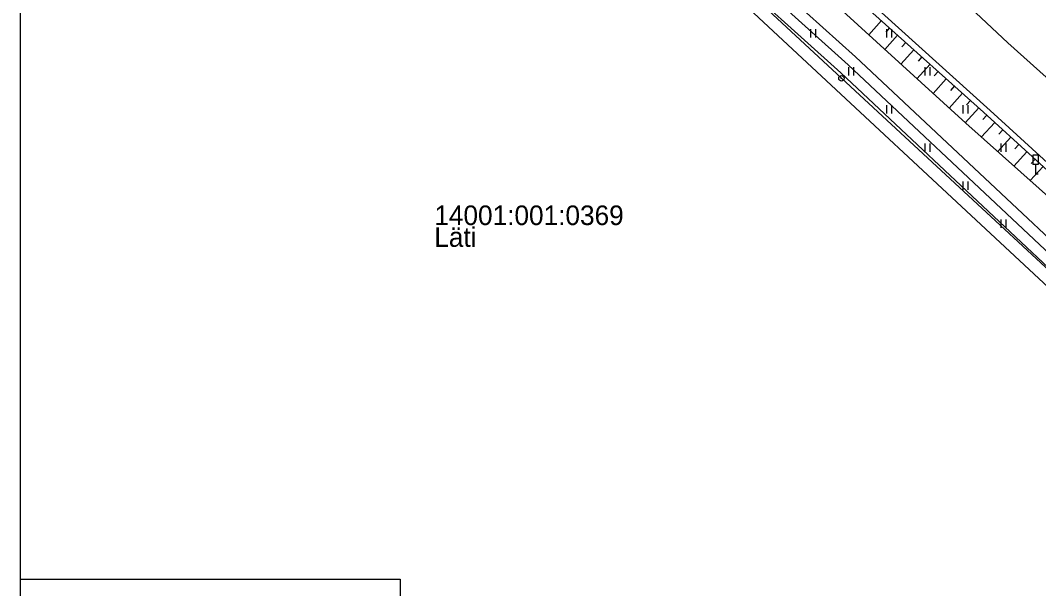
# Model space of a CAD drawing. Extents: x 567864 to 568657, y 6579839 to 6580994.
# Drawn here: x 568384.7 to 568478.2, y 6580358.5 to 6580410.7 of the extents above; entities that cross this region are included whole.
import ezdxf

# ---------------------------------------------------------------- set-up
doc = ezdxf.new("R2010")
doc.units = 0
for name, color, linetype in [('HALJASTUS', 7, 'Continuous'), ('KASUTUSALA', 7, 'Continuous'), ('KPOHULIIN', 7, 'Continuous'), ('LIIKLUS', 7, 'Continuous'), ('PIIR', 7, 'Continuous'), ('POST', 7, 'Continuous'), ('PR_SIDE', 7, 'Continuous'), ('RELJEEF', 7, 'Continuous'), ('TEE', 7, 'Continuous'), ('VORMISTUS_3', 7, 'Continuous')]:
    doc.layers.add(name, color=color, linetype=linetype)

msp = doc.modelspace()

# ---------------------------------------------------------------- linework, layer by layer
at = {"layer": 'HALJASTUS'}
for p, q in [((568457.272, 6580409.881), (568457.272, 6580409.119)), ((568457.728, 6580409.881), (568457.728, 6580409.119)), ((568464.272, 6580409.881), (568464.272, 6580409.119)), ((568464.728, 6580409.881), (568464.728, 6580409.119)), ((568460.772, 6580406.381), (568460.772, 6580405.619)), ((568461.228, 6580406.381), (568461.228, 6580405.619)), ((568467.772, 6580406.381), (568467.772, 6580405.619)), ((568468.228, 6580406.381), (568468.228, 6580405.619)), ((568464.272, 6580402.881), (568464.272, 6580402.119)), ((568464.728, 6580402.881), (568464.728, 6580402.119)), ((568471.272, 6580402.881), (568471.272, 6580402.119)), ((568471.728, 6580402.881), (568471.728, 6580402.119)), ((568467.772, 6580399.381), (568467.772, 6580398.619)), ((568468.228, 6580399.381), (568468.228, 6580398.619)), ((568474.772, 6580399.381), (568474.772, 6580398.619)), ((568475.228, 6580399.381), (568475.228, 6580398.619)), ((568471.272, 6580395.881), (568471.272, 6580395.119)), ((568471.728, 6580395.881), (568471.728, 6580395.119)), ((568474.772, 6580392.381), (568474.772, 6580391.619)), ((568475.228, 6580392.381), (568475.228, 6580391.619))]:
    msp.add_line(p, q, dxfattribs=at)
at = {"layer": 'KASUTUSALA'}
msp.add_lwpolyline([(568493.207, 6580374.737), (568460.062, 6580405.872), (568437.58, 6580426.106), (568418.255, 6580443.353), (568417.794, 6580443.764), (568417.1, 6580444.45), (568402.76, 6580458.616), (568388.236, 6580470.827), (568387.31, 6580471.69), (568385.679, 6580473.21), (568386.212, 6580473.528), (568388.359, 6580473.336), (568404.109, 6580460.095), (568418.602, 6580445.777), (568429.97, 6580456.218), (568431.455, 6580454.865), (568420.072, 6580444.412), (568438.915, 6580427.595), (568461.416, 6580407.344), (568494.568, 6580376.202)], dxfattribs=at)
at = {"layer": 'KPOHULIIN'}
msp.add_lwpolyline([(568508.43, 6580360.63), (568460.118, 6580405.359), (568402.883, 6580458.504), (568384.68, 6580466.246)], dxfattribs=at)
at = {"layer": 'LIIKLUS'}
for p, q in [((568477.701, 6580398.29), (568477.701, 6580397.44)), ((568478.201, 6580398.29), (568477.701, 6580398.29)), ((568478.201, 6580397.44), (568477.701, 6580397.44)), ((568477.951, 6580397.44), (568477.951, 6580396.54)), ((568478.201, 6580398.29), (568478.201, 6580397.44)), ((568478.201, 6580396.54), (568477.951, 6580396.54))]:
    msp.add_line(p, q, dxfattribs=at)
at = {"layer": 'PIIR'}
for points in [[(568508.43, 6580358.861), (568387.31, 6580471.69), (568384.68, 6580474.141)], [(568384.68, 6580470.154), (568387.31, 6580471.69), (568508.43, 6580358.861)]]:
    msp.add_lwpolyline(points, dxfattribs=at)
at = {"layer": 'POST'}
for radius in [0.25, 0.0234]:
    msp.add_circle((568460.118, 6580405.359), radius, dxfattribs=at)
at = {"layer": 'PR_SIDE'}
msp.add_lwpolyline([(568418.48, 6580444.494), (568438.248, 6580426.851), (568460.739, 6580406.609), (568493.888, 6580375.47), (568520.606, 6580350.928), (568532.176, 6580339.842), (568577.376, 6580298.14), (568583.801, 6580292.735), (568596.758, 6580277.054), (568604.332, 6580268.007), (568619.547, 6580250.982), (568628.574, 6580238.417), (568627.426, 6580222.172)], dxfattribs=at)
at = {"layer": 'RELJEEF'}
for p, q in [((568463.792, 6580410.661), (568462.629, 6580409.362)), ((568464.537, 6580409.994), (568464.186, 6580409.602)), ((568465.282, 6580409.326), (568464.106, 6580408.013)), ((568466.027, 6580408.659), (568465.672, 6580408.263)), ((568466.771, 6580407.992), (568465.582, 6580406.665)), ((568467.516, 6580407.325), (568467.158, 6580406.925)), ((568468.261, 6580406.658), (568467.059, 6580405.316)), ((568469.006, 6580405.991), (568468.644, 6580405.586)), ((568469.751, 6580405.323), (568468.536, 6580403.967)), ((568471.241, 6580403.989), (568470.013, 6580402.619)), ((568470.496, 6580404.656), (568470.13, 6580404.247)), ((568471.986, 6580403.322), (568471.615, 6580402.909)), ((568472.731, 6580402.655), (568471.49, 6580401.27)), ((568474.212, 6580401.311), (568472.97, 6580399.95)), ((568473.473, 6580401.985), (568473.098, 6580401.574)), ((568474.951, 6580400.637), (568474.581, 6580400.231)), ((568475.69, 6580399.963), (568474.463, 6580398.619)), ((568476.428, 6580399.289), (568476.063, 6580398.889)), ((568477.167, 6580398.615), (568475.957, 6580397.288)), ((568477.906, 6580397.942), (568477.545, 6580397.546)), ((568478.645, 6580397.268), (568477.45, 6580395.957))]:
    msp.add_line(p, q, dxfattribs=at)
for points in [[(568508.43, 6580369.908), (568508.363, 6580369.97), (568491.192, 6580385.824), (568473.185, 6580402.248), (568453.996, 6580419.435), (568439.254, 6580432.576), (568424.484, 6580446.124), (568410.28, 6580459.769), (568392.732, 6580475.544), (568387.587, 6580476.456), (568384.68, 6580475.798)], [(568508.43, 6580367.153), (568506.784, 6580368.671), (568490.34, 6580384.468), (568471.539, 6580401.225), (568453.41, 6580417.781), (568436.551, 6580429.766), (568424.43, 6580443.611), (568407.632, 6580458.36), (568391.91, 6580472.015), (568385.007, 6580473.1), (568384.68, 6580472.903)]]:
    msp.add_lwpolyline(points, dxfattribs=at)
at = {"layer": 'TEE'}
for points in [[(568508.43, 6580378.848), (568495.331, 6580390.846), (568482.748, 6580402.025), (568475.413, 6580408.617), (568468.573, 6580415.051), (568463.218, 6580419.847), (568458.453, 6580424.255), (568444.275, 6580436.505), (568431.318, 6580448.81), (568430.178, 6580450.348), (568426.969, 6580453.169), (568425.251, 6580454.077), (568411.891, 6580467.485), (568409.943, 6580469.266), (568402.862, 6580475.838), (568393.707, 6580484.18), (568385.876, 6580491.456)], [(568384.68, 6580477.004), (568386.096, 6580477.365), (568389.562, 6580477.715), (568393.349, 6580475.969), (568411.045, 6580459.971), (568424.789, 6580447.111), (568440.147, 6580432.905), (568454.13, 6580420.179), (568473.798, 6580402.405), (568491.299, 6580386.419), (568508.43, 6580370.472)]]:
    msp.add_lwpolyline(points, dxfattribs=at)
at = {"layer": 'VORMISTUS_3'}
for points in [[(568508.43, 6580333.956), (568384.68, 6580333.956), (568384.68, 6580491.456), (568508.43, 6580491.456)], [(568384.68, 6580351.956), (568384.68, 6580359.327), (568419.57, 6580359.327), (568419.57, 6580351.956)]]:
    msp.add_lwpolyline(points, close=True, dxfattribs=at)

# ---------------------------------------------------------------- texts
at = {"layer": 'PIIR'}
for s, p in [('14001:001:0369', (568422.713, 6580391.873)), ('Läti', (568422.713, 6580389.873))]:
    msp.add_text(s, height=1.8, dxfattribs=at).set_placement(p)

doc.saveas('drawing.dxf')
